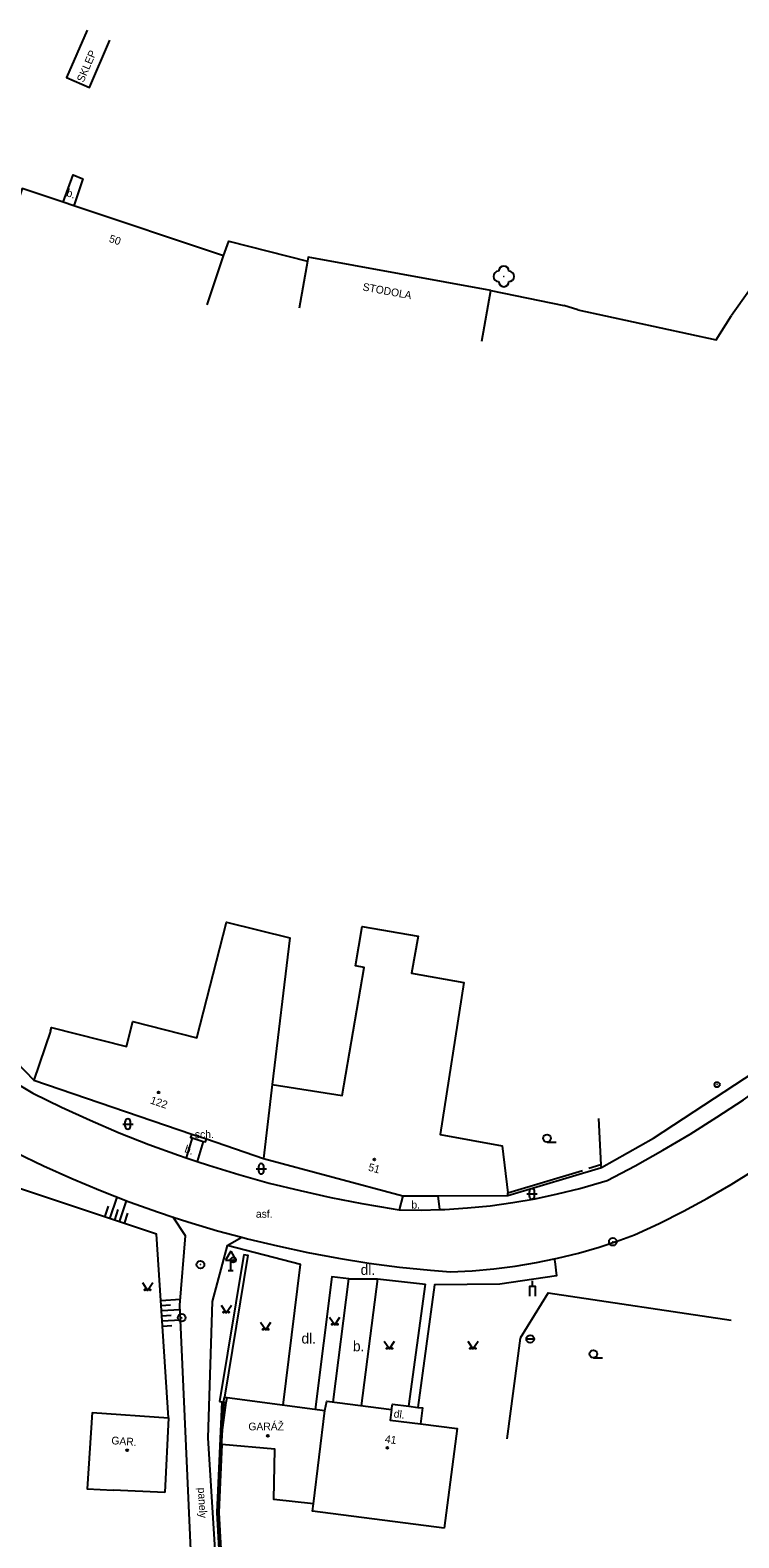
# Model space of a CAD drawing. Extents: x -582162 to -561283, y -1187583 to -1183539.
# Drawn here: x -570097.8 to -570029.1, y -1185372 to -1185225.8 of the extents above; entities that cross this region are included whole.
import ezdxf

# ---------------------------------------------------------------- set-up
doc = ezdxf.new("R2010")
doc.units = 0
for name, color, linetype in [('Vrstva 1', 7, 'Continuous'), ('Vrstva 10', 7, 'Continuous'), ('Vrstva 11', 7, 'Continuous'), ('Vrstva 12', 7, 'Continuous'), ('Vrstva 13', 7, 'Continuous'), ('Vrstva 14', 7, 'Continuous'), ('Vrstva 3', 7, 'Continuous'), ('Vrstva 4', 7, 'Continuous'), ('Vrstva 5', 7, 'Continuous'), ('Vrstva 6', 7, 'Continuous'), ('Vrstva 8', 7, 'Continuous'), ('Vrstva 9', 7, 'Continuous')]:
    doc.layers.add(name, color=color, linetype=linetype)

# ---------------------------------------------------------------- blocks, each defined once
blk = doc.blocks.new('1.079')
at = {"layer": 'Vrstva 1'}
for radius in [0.75, 0.001]:
    blk.add_circle((0, -0.001), radius, dxfattribs=at)
blk = doc.blocks.new('3.130')
at = {"layer": 'Vrstva 1'}
blk.add_circle((0, 0), 0.001, dxfattribs=at)
for centre, start, end in [((-1, 0), 90, 270), ((0, 1), 0, 180), ((1, 0), 270, 90), ((0, -1), 180, 360)]:
    blk.add_arc(centre, 1, start, end, dxfattribs=at)
blk = doc.blocks.new('3.040')
at = {"layer": 'Vrstva 1'}
blk.add_line((0, -0.75), (1.75, -0.75), dxfattribs=at)
blk.add_circle((0, 0), 0.75, dxfattribs=at)
blk = doc.blocks.new('3.140')
at = {"layer": 'Vrstva 1'}
blk.add_lwpolyline([(-1, 1.5), (0, 0), (1, 1.5)], dxfattribs=at)
for centre in [(-0.5, 0.1), (0.5, 0.1)]:
    blk.add_circle(centre, 0.1, dxfattribs=at)
blk = doc.blocks.new('3.160')
at = {"layer": 'Vrstva 1'}
for p, q in [((-1, 0), (1, 0)), ((-0.5, -0.5), (-0.5, 0.5)), ((0.5, -0.5), (0.5, 0.5))]:
    blk.add_line(p, q, dxfattribs=at)
for centre, start, end in [((0, 0.5), 0, 180), ((0, -0.5), 180, 360)]:
    blk.add_arc(centre, 0.5, start, end, dxfattribs=at)
blk = doc.blocks.new('4.020')
at = {"layer": 'Vrstva 1'}
blk.add_circle((0, 0), 0.175, dxfattribs=at)
blk = doc.blocks.new('4.110')
at = {"layer": 'Vrstva 1'}
for radius in [0.5, 0.001]:
    blk.add_circle((-0.001, 0), radius, dxfattribs=at)
blk = doc.blocks.new('4.120')
at = {"layer": 'Vrstva 1'}
blk.add_line((0, 2), (0, 3), dxfattribs=at)
blk.add_lwpolyline([(-0.5, 0), (-0.5, 2), (0.5, 2), (0.5, 0)], dxfattribs=at)
blk = doc.blocks.new('5.270')
at = {"layer": 'Vrstva 1'}
for p, q in [((0, 3.732), (-1, 2)), ((0, 3.732), (1, 2)), ((-1, 2), (1, 2)), ((-0.5, 0), (0.5, 0)), ((0, 0), (0, 2))]:
    blk.add_line(p, q, dxfattribs=at)
blk = doc.blocks.new('8.110')
at = {"layer": 'Vrstva 1'}
blk.add_line((-0.75, 0), (0.75, 0), dxfattribs=at)
blk.add_circle((0, 0), 0.75, dxfattribs=at)

msp = doc.modelspace()

# ---------------------------------------------------------------- linework, layer by layer
at = {"layer": 'Vrstva 10'}
for points in [[(-570094.6, -1185242.49), (-570093.63, -1185239.82), (-570092.69, -1185240.23), (-570093.57, -1185242.83)], [(-570042.37, -1185336.1), (-570037.35, -1185333.27), (-570024.58, -1185324.9), (-570005.47, -1185311.9), (-570002.74, -1185310.14), (-570000, -1185308.46)], [(-570041.84, -1185337.36), (-570039.12, -1185335.93), (-570036.43, -1185334.44), (-570033.79, -1185332.87), (-570031.18, -1185331.23), (-570028.62, -1185329.53), (-570026.11, -1185327.76), (-570023.8, -1185326.05), (-570004.73, -1185313.06), (-570001.8, -1185311.2), (-570000, -1185310.12)], [(-570036.78, -1185341.53), (-570034.42, -1185340.34), (-570032.1, -1185339.09), (-570029.81, -1185337.76), (-570027.56, -1185336.37), (-570025.36, -1185334.9), (-570023.21, -1185333.38), (-570021.1, -1185331.78), (-570019.22, -1185330.28), (-570002.35, -1185318.91), (-570000.95, -1185317.79), (-570000, -1185317.1)], [(-570110.07, -1185319.33), (-570108.32, -1185320.95), (-570106.52, -1185322.51), (-570104.67, -1185324.01), (-570102.77, -1185325.44), (-570100.82, -1185326.81), (-570098.83, -1185328.12), (-570097.54, -1185328.91), (-570094.78, -1185330.26), (-570091.99, -1185331.53), (-570089.16, -1185332.73), (-570086.3, -1185333.86), (-570083.42, -1185334.91), (-570082.68, -1185335.16)], [(-570082.09, -1185333.24), (-570082.68, -1185335.16)], [(-570082.13, -1185332.86), (-570082.24, -1185333.19), (-570082.09, -1185333.24)], [(-570082.09, -1185333.24), (-570081.02, -1185333.57)], [(-570081.02, -1185333.57), (-570080.81, -1185333.63), (-570080.71, -1185333.34)], [(-570099.21, -1185334.64), (-570096.5, -1185335.95), (-570093.77, -1185337.18), (-570090.99, -1185338.34), (-570088.19, -1185339.43), (-570085.36, -1185340.44), (-570083.94, -1185340.91)], [(-570081.02, -1185333.57), (-570081.62, -1185335.51)], [(-570082.68, -1185335.16), (-570081.62, -1185335.51)], [(-570081.62, -1185335.51), (-570080.5, -1185335.88), (-570077.57, -1185336.78), (-570074.61, -1185337.61), (-570071.63, -1185338.35), (-570068.63, -1185339.02), (-570065.62, -1185339.61), (-570062.59, -1185340.12), (-570062.01, -1185340.21)], [(-570058.09, -1185340.18), (-570057.59, -1185340.17), (-570055.38, -1185340.03), (-570053.18, -1185339.81), (-570050.99, -1185339.51), (-570048.81, -1185339.13), (-570046.64, -1185338.67), (-570044.5, -1185338.14), (-570042.37, -1185337.53), (-570041.84, -1185337.36)], [(-570061.66, -1185338.87), (-570062.01, -1185340.21)], [(-570058.26, -1185338.85), (-570058.09, -1185340.18)], [(-570062.01, -1185340.21), (-570059.8, -1185340.23), (-570058.09, -1185340.18)], [(-570081.18, -1185396.24), (-570083.28, -1185349.47), (-570082.73, -1185342.72), (-570083.94, -1185340.91)], [(-570083.94, -1185340.91), (-570082.51, -1185341.38), (-570079.63, -1185342.24), (-570077.28, -1185342.87)], [(-570046.96, -1185344.96), (-570046.64, -1185344.9), (-570044.61, -1185344.4), (-570042.6, -1185343.82), (-570040.6, -1185343.16), (-570039.18, -1185342.64), (-570036.78, -1185341.53)], [(-570078.69, -1185343.68), (-570080.15, -1185349.1), (-570080.56, -1185362.33), (-570078.46, -1185396.03)], [(-570078.69, -1185343.68), (-570077.28, -1185342.87)], [(-570073.26, -1185359.15), (-570071.57, -1185345.51), (-570078.69, -1185343.68)], [(-570077.28, -1185342.87), (-570076.73, -1185343.02), (-570073.81, -1185343.72), (-570070.87, -1185344.35), (-570067.91, -1185344.9), (-570064.94, -1185345.37), (-570061.97, -1185345.76), (-570058.98, -1185346.07), (-570057.02, -1185346.23), (-570054.93, -1185346.12), (-570052.84, -1185345.94), (-570050.76, -1185345.67), (-570048.69, -1185345.32), (-570046.96, -1185344.96)], [(-570077.09, -1185344.54), (-570079.44, -1185358.8)], [(-570046.96, -1185344.96), (-570046.92, -1185345.23), (-570046.74, -1185346.61), (-570052.25, -1185347.43), (-570058.57, -1185347.5), (-570060.21, -1185359.37)], [(-570068.4, -1185358.86), (-570066.91, -1185346.92), (-570068.56, -1185346.72), (-570070.15, -1185359.57)], [(-570066.91, -1185346.92), (-570064.13, -1185346.89)], [(-570064.13, -1185346.89), (-570065.69, -1185359.21)], [(-570064.13, -1185346.89), (-570059.47, -1185347.41)], [(-570061.08, -1185359.25), (-570059.47, -1185347.41)], [(-570062.75, -1185359.59), (-570062.66, -1185359.05), (-570061.08, -1185359.25)], [(-570061.08, -1185359.25), (-570060.21, -1185359.37)], [(-570060.21, -1185359.37), (-570059.75, -1185359.43), (-570059.95, -1185360.98)]]:
    msp.add_lwpolyline(points, dxfattribs=at)
at = {"layer": 'Vrstva 12'}
for points in [[(-570084.4, -1185360.4), (-570085.54, -1185342.58), (-570100.4, -1185337.63)], [(-570090.08, -1185341.07), (-570089.38, -1185338.97)], [(-570089.13, -1185341.38), (-570088.45, -1185339.33)], [(-570090.55, -1185340.91), (-570090.2, -1185339.85)], [(-570089.61, -1185341.23), (-570089.26, -1185340.19)], [(-570088.66, -1185341.54), (-570088.32, -1185340.52)], [(-570085.13, -1185349), (-570083.23, -1185348.87)], [(-570085.1, -1185349.49), (-570084.19, -1185349.44)], [(-570085.07, -1185349.99), (-570083.26, -1185349.88)], [(-570085.03, -1185350.49), (-570084.14, -1185350.44)], [(-570085, -1185350.99), (-570083.22, -1185350.88)], [(-570084.97, -1185351.49), (-570084.08, -1185351.43)]]:
    msp.add_lwpolyline(points, dxfattribs=at)
at = {"layer": 'Vrstva 4'}
for points in [[(-570092.28, -1185225.8), (-570094.27, -1185230.39), (-570092.06, -1185231.35), (-570090.07, -1185226.76)], [(-570094.6, -1185242.49), (-570098.59, -1185241.15), (-570100.18, -1185245.89)], [(-570093.57, -1185242.83), (-570094.6, -1185242.49)], [(-570079.04, -1185247.69), (-570093.57, -1185242.83)], [(-570080.63, -1185252.43), (-570079.04, -1185247.69)], [(-570070.9, -1185248.19), (-570071.72, -1185252.75)], [(-570053.11, -1185251.05), (-570070.83, -1185247.83), (-570070.9, -1185248.19)], [(-570054, -1185255.97), (-570053.11, -1185251.05)], [(-570095.85, -1185322.9), (-570097.46, -1185327.63)], [(-570097.46, -1185327.63), (-570082.13, -1185332.86)], [(-570082.13, -1185332.86), (-570080.71, -1185333.34)], [(-570080.71, -1185333.34), (-570075.18, -1185335.23)], [(-570075.18, -1185335.23), (-570061.66, -1185338.87)], [(-570061.66, -1185338.87), (-570058.26, -1185338.85)], [(-570058.26, -1185338.85), (-570051.46, -1185338.81)], [(-570051.46, -1185338.81), (-570051.46, -1185338.55)], [(-570079.17, -1185361.8), (-570078.78, -1185358.91)], [(-570078.78, -1185358.91), (-570078.71, -1185358.42)], [(-570078.71, -1185358.42), (-570069.23, -1185359.69)], [(-570069.23, -1185359.69), (-570069.04, -1185358.78), (-570062.75, -1185359.59)], [(-570062.75, -1185359.59), (-570062.88, -1185360.6), (-570059.95, -1185360.98)], [(-570091.79, -1185359.88), (-570084.4, -1185360.4), (-570084.76, -1185367.64)], [(-570059.95, -1185360.98), (-570056.4, -1185361.43), (-570057.65, -1185371.09)], [(-570084.76, -1185367.64), (-570089.75, -1185367.39)]]:
    msp.add_lwpolyline(points, dxfattribs=at)
at = {"layer": 'Vrstva 5'}
for points in [[(-570095.85, -1185322.9), (-570095.73, -1185322.52), (-570088.47, -1185324.38), (-570087.85, -1185321.95), (-570081.65, -1185323.54), (-570078.77, -1185312.31), (-570072.63, -1185313.84), (-570074.33, -1185328.06), (-570075.18, -1185335.23)], [(-570074.33, -1185328.06), (-570067.55, -1185329.11), (-570065.4, -1185316.71), (-570066.26, -1185316.56), (-570065.59, -1185312.72), (-570060.17, -1185313.66), (-570060.8, -1185317.27), (-570055.75, -1185318.15), (-570058.05, -1185332.89), (-570052.02, -1185334.02), (-570051.46, -1185338.55)], [(-570070.32, -1185368.74), (-570069.23, -1185359.69)], [(-570091.79, -1185359.88), (-570092.28, -1185367.27), (-570089.75, -1185367.39)], [(-570057.65, -1185371.09), (-570070.41, -1185369.45), (-570070.32, -1185368.74), (-570074.16, -1185368.31), (-570074.08, -1185363.44), (-570079.22, -1185362.97), (-570079.17, -1185361.8)]]:
    msp.add_lwpolyline(points, dxfattribs=at)
at = {"layer": 'Vrstva 9'}
for points in [[(-570079.04, -1185247.69), (-570078.55, -1185246.28), (-570070.9, -1185248.19)], [(-570053.11, -1185251.05), (-570046.04, -1185252.5)], [(-570028.1, -1185251.11), (-570029.77, -1185253.47)], [(-570044.69, -1185252.93), (-570046.04, -1185252.5)], [(-570044.69, -1185252.93), (-570031.27, -1185255.83), (-570029.77, -1185253.47)], [(-570109.5, -1185315.17), (-570097.46, -1185327.63)], [(-570042.66, -1185331.34), (-570042.44, -1185335.86)], [(-570051.46, -1185338.81), (-570042.37, -1185336.1)], [(-570051.46, -1185338.55), (-570044.24, -1185336.4)], [(-570042.44, -1185335.86), (-570043.62, -1185336.21)], [(-570042.37, -1185336.1), (-570042.44, -1185335.86)], [(-570077.09, -1185344.54), (-570076.69, -1185344.61), (-570078.96, -1185358.39)], [(-570047.57, -1185348.26), (-570050.29, -1185352.66)], [(-570047.57, -1185348.26), (-570029.8, -1185350.92)], [(-570050.29, -1185352.66), (-570051.58, -1185362.41)], [(-570079.22, -1185358.83), (-570079.69, -1185369.58), (-570078.08, -1185399.17)], [(-570079.44, -1185358.8), (-570079.22, -1185358.83)], [(-570079.22, -1185358.83), (-570079.04, -1185358.86)], [(-570079.04, -1185358.86), (-570079.17, -1185361.8)], [(-570079.04, -1185358.86), (-570078.96, -1185358.39)], [(-570079.04, -1185358.86), (-570078.78, -1185358.91)], [(-570078.96, -1185358.39), (-570078.71, -1185358.42)], [(-570079.22, -1185362.97), (-570079.51, -1185369.58), (-570077.9, -1185399.17)]]:
    msp.add_lwpolyline(points, dxfattribs=at)

# ---------------------------------------------------------------- block references
at = {"layer": 'Vrstva 1', "xscale": 0.5, "yscale": 0.5}
for p in [(-570041.28, -1185343.31), (-570081.29, -1185345.52), (-570083.11, -1185350.68)]:
    msp.add_blockref('1.079', p, dxfattribs=at)
at = {"layer": 'Vrstva 11', "xscale": 0.5, "yscale": 0.5}
msp.add_blockref('3.130', (-570051.86, -1185249.68), dxfattribs=at)
at = {"layer": 'Vrstva 3', "xscale": 0.5, "yscale": 0.5}
for name, p in [('3.160', (-570088.33, -1185331.89)), ('3.040', (-570047.67, -1185333.27)), ('3.160', (-570075.39, -1185336.23)), ('3.160', (-570049.13, -1185338.67)), ('3.140', (-570086.42, -1185348.02)), ('3.140', (-570078.79, -1185350.2)), ('3.140', (-570068.26, -1185351.37)), ('3.140', (-570074.96, -1185351.85)), ('3.140', (-570062.96, -1185353.7)), ('3.140', (-570054.86, -1185353.7)), ('3.040', (-570043.17, -1185354.19))]:
    msp.add_blockref(name, p, dxfattribs=at)
at = {"layer": 'Vrstva 8', "xscale": 0.5, "yscale": 0.5}
for p in [(-570085.35, -1185328.82), (-570064.42, -1185335.33), (-570074.75, -1185362.13), (-570088.4, -1185363.53), (-570063.16, -1185363.29)]:
    msp.add_blockref('4.020', p, dxfattribs=at)
at = {"layer": 'Vrstva 9', "xscale": 0.5, "yscale": 0.5}
for name, p in [('4.110', (-570031.17, -1185328.07)), ('5.270', (-570078.35, -1185346.09)), ('4.110', (-570078.11, -1185345.07)), ('4.120', (-570049.08, -1185348.6)), ('8.110', (-570049.3, -1185352.73))]:
    msp.add_blockref(name, p, dxfattribs=at)

# ---------------------------------------------------------------- texts
at = {"layer": 'Vrstva 13'}
for s, p in [('dl.', (-570065.75, -1185346.52)), ('dl.', (-570071.49, -1185353.18)), ('b.', (-570066.5, -1185353.93))]:
    msp.add_text(s, height=1, dxfattribs=at).set_placement(p)
at = {"layer": 'Vrstva 14'}
for s, rotation, p in [('SKLEP', 66.583, (-570092.63, -1185230.92)), ('b.', 341.504, (-570094.35, -1185241.88)), ('STODOLA', 349.701, (-570065.6, -1185251.04)), (' b.', 341.165, (-570083.16, -1185334.53)), (' b.', 0.337, (-570061.1, -1185340.09)), (' dl.', 352.56, (-570062.85, -1185360.3)), (' GAR.', 355.975, (-570090.23, -1185362.92)), ('panely', 272.803, (-570081.53, -1185367.17))]:
    msp.add_text(s, height=0.75, rotation=rotation, dxfattribs=at).set_placement(p)
for s, p in [('sch.', (-570081.83, -1185333.26)), ('asf.', (-570075.91, -1185340.98)), ('GARÁŽ', (-570076.64, -1185361.6))]:
    msp.add_text(s, height=0.75, dxfattribs=at).set_placement(p)
at = {"layer": 'Vrstva 6'}
for s, rotation, p in [('50', 341.504, (-570090.22, -1185246.32)), ('122', 341.165, (-570086.22, -1185329.88)), ('51', 344.932, (-570065.07, -1185336.4)), ('41', 352.666, (-570063.43, -1185362.79))]:
    msp.add_text(s, height=0.75, rotation=rotation, dxfattribs=at).set_placement(p)

doc.saveas('drawing.dxf')
